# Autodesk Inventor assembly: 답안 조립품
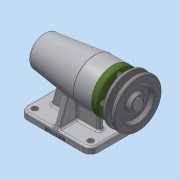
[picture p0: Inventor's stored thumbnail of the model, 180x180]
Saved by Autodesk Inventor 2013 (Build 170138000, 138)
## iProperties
Created: 2018-09
Part Number: 답안 조립품
Document SubType Name: Assembly
Designer: dgall
Author: dgall
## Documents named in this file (12)
- C:\Users\dgall\Desktop\480907V1019\답안 조립품.iam
- C:\Users\dgall\Desktop\480907V1019\2018-09-22 본체.ipt
- C:\Users\dgall\Desktop\480907V1019\볼트 M4.ipt
- C:\Users\dgall\Desktop\480907V1019\베어링 6004.ipt
- C:\Users\dgall\Desktop\480907V1019\V벨트풀리.ipt
- C:\Users\dgall\Desktop\480907V1019\멈춤나사 M3.ipt
- C:\Users\dgall\Desktop\480907V1019\베어링 51202.ipt
- C:\Users\dgall\Desktop\480907V1019\어댑터슬리브.ipt
- C:\Users\dgall\Desktop\480907V1019\오일 실.ipt
- C:\Users\dgall\Desktop\480907V1019\축.ipt
- C:\Users\dgall\Desktop\480907V1019\커버.ipt
- C:\Users\dgall\Desktop\480907V1019\키 5 x 5 x 16.ipt
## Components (2 placed, 2 different names)
1. 2018-09-22 본체:1 — 각도:1
2. V벨트풀리:1 — 플러쉬:1
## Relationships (2: Angle 1, Flush 1)
- 각도:1 [Angle]: 2018-09-22 본체:1
- 플러쉬:1 [Flush]: V벨트풀리:1
